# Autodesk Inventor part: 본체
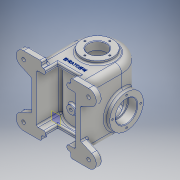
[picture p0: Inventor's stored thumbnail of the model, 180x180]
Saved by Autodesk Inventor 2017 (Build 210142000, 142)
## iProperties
Part Number: 본체
Material: 알루미늄 6061
Document SubType Name: Modeling
Designer: MRC
Density: 2.7 g/cm^3
Appearance: 알루미늄 - 평지
Mass: 1386.3 g
Surface Area: 1149.79 cm^2
Volume: 513.445 cm^3
Author: MRC
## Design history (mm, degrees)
sketch "스케치1"
  geometry: L1 (-45, 0)-(-45, -76); L2 (-45, -76)-(45, -76); L3 (45, -76)-(45, 0); A1 r 45 centre (0, 0) between (45, 0) and (-45, 0); 1 further point
  constraints: 6 end point, 2 point on circle, 2 tangent, 1 centre point, 1 coincident, 1 perpendicular, 1 vertical
  dimensions: "d0" = 90 diameter of A1; "d1" = 76 distance of L1.start L1.end; "d2" = 90 distance of L1.end L2.end
extrude "돌출1" new body sketch "스케치1" stored distance "d3" = 108; taper "d4" = 0 deg
node "작업 평면1"
sketch "스케치5"
  geometry: C1 r 28.5 at (0, 0); 1 further point
  constraints: 1 centre point, 1 coincident
  dimensions: "d22" = 57 diameter of C1
extrude "돌출4" join sketch "스케치5" distance "d23" = 6; taper "d24" = 0 deg
sketch "스케치6"
  geometry: C1 r 16.5 at (0, 0); 1 further point
  constraints: 1 centre point, 1 coincident
  dimensions: "d25" = 33 diameter of C1
extrude "돌출5" cut sketch "스케치6" distance "d26" = 15; taper "d27" = 0 deg
sketch "스케치7" dims "d28" = 46
  geometry: 3 further points
  constraints: 2 horizontal alignment, 1 coincident, 2 other
hole "구멍2" sketch "스케치7" at (23, 0) diameter "d29" = 3.242; stored, may be unused: countersink angle "d33" = 90 deg, drill point angle "d35" = 118 deg; dims "d30" = 8, "d31" = 4, "d32" = 2, "d34" = 10
node "작업 평면2"
node "작업 평면3"
sketch "스케치11"
  geometry: L1 (73.5, 6)-(16.5, 6) reference; C1 r 7.5 at (45, -68); 1 further point
  constraints: 1 centre point
  dimensions: "d52" = 15 diameter of C1; "d53" = 74 distance from line of L1 C1.centre
extrude "돌출7" join sketch "스케치11" stored distance "d54" = 15; taper "d55" = 0 deg
sketch "스케치12"
  geometry: C1 r 7.5 at (0, 0) reference; 2 further points
  constraints: 1 coincident
hole "구멍4" sketch "스케치12" at (0, 0) diameter "d56" = 5.188; stored, may be unused: countersink angle "d60" = 90 deg, drill point angle "d62" = 118 deg; dims "d57" = 18, "d58" = 4, "d59" = 2, "d61" = 20
node "작업 평면4"
sketch "스케치13"
  geometry: L1 (45, -76)-(-45, -76) reference; L2 (0, -76)-(20, -76); L3 (20, -76)-(20, -53); L4 (20, -53)-(-20, -53); L5 (-20, -53)-(-20, -76); 1 further point
  constraints: 8 end point, 3 perpendicular, 2 point on line, 1 midpoint
  dimensions: "d63" = 20 distance of L2.start L2.end; "d64" = 23 distance of L2.end L3.end; "d65" = 40 distance of L3.end L4.end
extrude "돌출8" cut sketch "스케치13" stored distance "d66" = 15; taper "d67" = 0 deg
node "작업 평면7"
sketch "스케치14"
  geometry: L1 (60, -64)-(-60, -64); L2 (-60, -64)-(-60, 36); L3 (-60, 36)-(60, 36); L4 (60, 36)-(60, -64); L5 (60, -64)-(-60, 36); L6 (-60, -64)-(60, 36); L7 (-60, 50)-(-27, 50); L8 (-27, 50)-(-27, 32.342); L9 (-27, 32.342)-(-36.742, 32.342); L10 (-36.742, 32.342)-(-36.742, 10.325); L11 (-36.742, 10.325)-(-65.693, 23.21); L12 (-45, -68)-(-45, 40) reference; L13 (-45, 14)-(-45, 50); A1 r 14 centre (-60, 36) between (-60, 50) and (-65.693, 23.21); 1 further point
  constraints: 24 end point, 4 perpendicular, 4 point on line, 2 horizontal, 2 midpoint, 2 parallel, 2 point on circle, 2 tangent, 1 centre point, 1 coincident
  dimensions: "d70" = 120 distance of L2.end L3.end; "d71" = 100 distance of L1.end L2.end; "d72" = 28 diameter of A1; "d73" = 18 distance between parallel lines of L8 L12; "d74" = 36 distance of L13.start L13.end
extrude "돌출9" join sketch "스케치14" distance "d75" = 12; taper "d76" = 0 deg
sketch "스케치15"
  geometry: L1 (-45, -64)-(-45, 0) reference; L2 (45, 0)-(45, -64) reference; L3 (-36, -76)-(-36, -27); L4 (36, -27)-(36, -76); L5 (-36, -76)-(36, -76); A1 r 45 centre (0, 0) between (-36, -27) and (36, -27); 2 further points
  constraints: 6 end point, 2 parallel, 2 point on circle, 1 centre point, 1 coincident, 1 horizontal, 1 point on line
  dimensions: "d77" = 9 distance between parallel lines of L3 L1; "d78" = 9 distance between parallel lines of L4 L2; "d79" = 90 diameter of A1
extrude "돌출10" cut sketch "스케치15" stored distance "d80" = 90; taper "d81" = 0 deg
sketch "스케치16"
  geometry: L1 (-6, 59.5)-(-6, 92.5) reference; L2 (0, 76)-(108, 76) reference; C1 r 31 at (68, 76); 1 further point
  constraints: 1 centre point, 1 point on line
  dimensions: "d84" = 62 diameter of C1; "d85" = 74 distance from line of L1 C1.centre
extrude "돌출11" join sketch "스케치16" stored distance "d86" = 108; taper "d87" = 0 deg
sketch "스케치17"
  geometry: C1 r 31 at (0, 0) reference; C2 r 20 at (0, 0); 1 further point
  constraints: 1 centre point, 1 coincident
  dimensions: "d88" = 40 diameter of C2
extrude "돌출12" cut sketch "스케치17" distance "d89" = 16; taper "d90" = 0 deg
node "작업 평면8"
sketch "스케치20"
  geometry: C1 r 36 at (0, 0); 1 further point
  constraints: 1 centre point, 1 coincident
extrude "돌출13" cut sketch "스케치20" stored distance "d93" = 90; taper "d94" = 0 deg
sketch "스케치22" dims "d95" = 52
  geometry: C1 r 31 at (0, 0) reference; 3 further points
  constraints: 2 vertical alignment, 1 coincident, 2 other
hole "구멍5" sketch "스케치22" at (0, 26) diameter "d96" = 3.242; stored, may be unused: countersink angle "d100" = 90 deg, drill point angle "d102" = 118 deg; dims "d97" = 8, "d98" = 4, "d99" = 2, "d101" = 10
sketch "스케치23"
  geometry: C1 r 31 at (0, 0) reference; C2 r 17.5 at (0, 0); 1 further point
  constraints: 1 centre point, 1 coincident
  dimensions: "d106" = 35 diameter of C2
extrude "돌출14" cut sketch "스케치23" stored distance "d107" = 90; taper "d108" = 0 deg
sketch "스케치24"
  geometry: C1 r 9 at (-60, 36); C2 r 9 at (60, 36); C3 r 9 at (60, -64); C4 r 9 at (-60, -64); A1 r 14 centre (-60, 36) between (-60, 50) and (-65.693, 23.21) reference; A2 r 14 centre (60, 36) between (65.693, 23.21) and (60, 50) reference; A3 r 14 centre (60, -64) between (60, -78) and (65.693, -51.21) reference; A4 r 14 centre (-60, -64) between (-65.693, -51.21) and (-60, -78) reference; 1 further point
  constraints: 4 centre point, 4 coincident
  dimensions: "d109" = 18 diameter of C1; "d110" = 18 diameter of C2; "d111" = 18 diameter of C3; "d112" = 18 diameter of C4
extrude "돌출15" cut sketch "스케치24" distance "d113" = 2; taper "d114" = 0 deg
sketch "스케치25"
  geometry: C1 r 9 at (0, 0) reference; C2 r 3.3 at (0, 0); C3 r 9 at (120, 0) reference; C4 r 3.3 at (120, 0); C5 r 9 at (120, -100) reference; C6 r 3.3 at (120, -100); C7 r 9 at (0, -100) reference; C8 r 3.3 at (0, -100); 1 further point
  constraints: 4 centre point, 4 coincident
  dimensions: "d115" = 6.6 diameter of C2; "d116" = 6.6 diameter of C4; "d117" = 6.6 diameter of C6; "d118" = 6.6 diameter of C8
extrude "돌출16" cut sketch "스케치25" stored distance "d119" = 2; taper "d120" = 0 deg
fillet "모깎기1" dims "d121" = 3
fillet "모깎기2" dims "d122" = 12
fillet "모깎기3" dims "d123" = 3
fillet "모깎기4" dims "d125" = 3
fillet "모깎기5" dims "d126" = 3
fillet "모깎기6" dims "d127" = 3
fillet "모깎기7" dims "d128" = 3
fillet "모깎기8" dims "d129" = 3
chamfer "모따기1" distance "d130" = 1; stored, may be unused: second distance "d131" = 2, angle "d132" = 45 deg
chamfer "모따기2" distance "d133" = 1; stored, may be unused: second distance "d134" = 2, angle "d135" = 45 deg
chamfer "모따기3" distance "d136" = 1; stored, may be unused: second distance "d137" = 2, angle "d138" = 45 deg
sketch "스케치26"
  geometry: L1 (-36, -27)-(-36, -31) reference; L2 (36, -31)-(36, -27) reference; L3 (-36, -27)-(-36, -76) reference; L4 (-36, -27)-(-36, -35); L5 (-36, -35)-(-28.284, -35); A1 r 45 centre (0, 0) between (-33, -30.594) and (33, -30.594) reference; A2 r 45 centre (0, 0) between (-28.634, -34.714) and (-28.284, -35); A3 r 45 centre (0, 0) between (-36, -27) and (-28.284, -35); 1 further point
  constraints: 5 point on circle, 4 end point, 2 centre point, 1 coincident, 1 horizontal, 1 point on line
  dimensions: "d140" = 8 distance from line of L1.start L5
extrude "돌출17" cut sketch "스케치26" stored distance "d141" = 70; taper "d142" = 0 deg
fillet "모깎기9" dims "d143" = 3
fillet "모깎기10" dims "d144" = 3
sketch "스케치27"
  geometry: L1 (-30, -76)-(-60, -76) reference; 2 further points
  constraints: 1 vertical alignment, 1 other
  dimensions: "d145" = 35 distance from line of L1 point (0, -41)
feature "엠보싱1" sketch "스케치27" dims "d25" = 33, "d146" = 0.5, "d147" = 0
node "솔리드1"
pattern_circular "원형 패턴2" dims angle "d37" = 360 deg
mirror "미러3"
mirror "미러4"
mirror "미러6"
pattern_circular "원형 패턴3" dims angle "d104" = 360 deg
mirror "미러7"
mirror "미러8"
mirror "미러9"
mirror "미러10"
other parameters: "d39" = -129, "d51" = -125, "d69" = -125
